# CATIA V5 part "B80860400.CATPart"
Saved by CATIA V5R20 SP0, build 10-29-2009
Part number: B80860400
Revision: 2
Definition: design
Nomenclature: B80860400
Source: made
Description: NOT SPECIFIED
Bounding box of the stored display mesh (mm): x -32.322 to 32.322, y -32.5 to 32.5, z 0 to 400
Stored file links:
  C:\Users\Raffaele\Desktop\3D X SITO CF\BOLEX\4-PILLAR REF 808\B80860400.CATPart
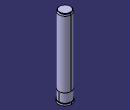
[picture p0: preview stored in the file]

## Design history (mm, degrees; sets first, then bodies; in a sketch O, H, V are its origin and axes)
Body1 "MANIFOLD_SOLID_BREP #450" (main body)
  Solid1: solid without history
